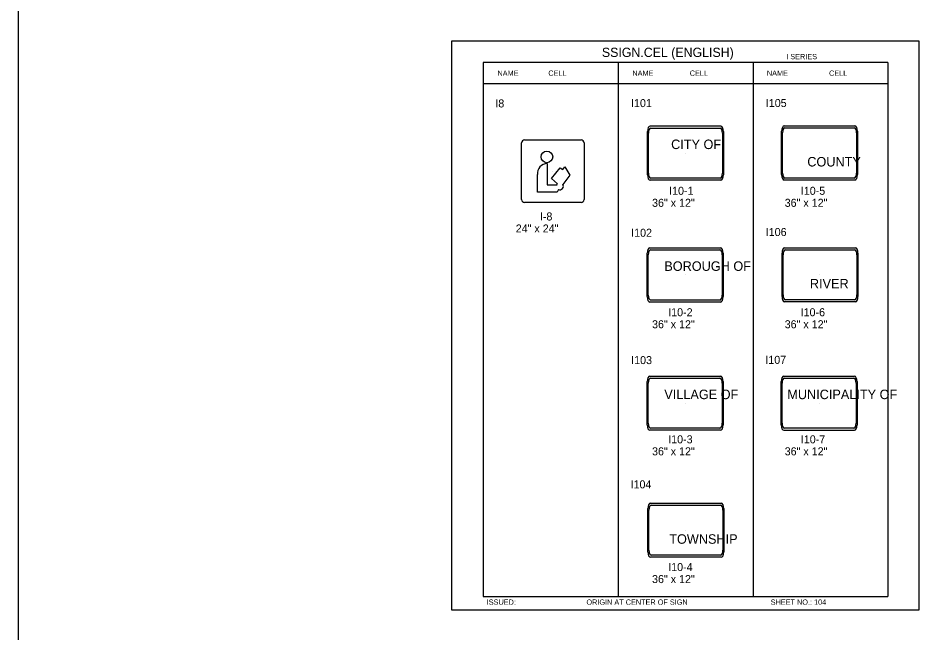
# Model space of a CAD drawing. Extents: x -5299 to 22597, y -19549 to -1808.
# Drawn here: x 13684 to 15035, y -4579 to -3658 of the extents above; entities that cross this region are included whole.
import ezdxf

# ---------------------------------------------------------------- set-up
doc = ezdxf.new("R2010")
doc.units = 0
for name, color, linetype in [('Level 1', 7, 'Continuous'), ('Level 2', 7, 'Continuous'), ('Level 3', 7, 'Continuous'), ('Level 61', 7, 'Continuous')]:
    doc.layers.add(name, color=color, linetype=linetype)

msp = doc.modelspace()

# ---------------------------------------------------------------- linework, layer by layer
at = {"layer": 'Level 1'}
for p, q in [((14988.9, -3724.4), (14381.9, -3724.4)), ((14381.9, -3724.4), (14381.9, -4524.4)), ((14584.3, -3724.4), (14584.3, -4524.4)), ((14786.6, -3724.4), (14786.6, -4524.4)), ((14988.9, -3724.4), (14988.9, -4524.4)), ((14988.9, -3756), (14381.9, -3756)), ((14632.2, -3819.4), (14738.4, -3819.4)), ((14633.3, -3822.5), (14737.3, -3822.5)), ((14833.3, -3819.1), (14939.5, -3819.1)), ((14834.4, -3822.1), (14938.4, -3822.1)), ((14628.4, -3892.6), (14628.4, -3827.6)), ((14629.8, -3890.2), (14629.8, -3830)), ((14740.8, -3830), (14740.8, -3890.2)), ((14742.2, -3827.6), (14742.2, -3892.6)), ((14829.5, -3892.3), (14829.5, -3827.3)), ((14830.9, -3889.9), (14830.9, -3829.7)), ((14941.9, -3829.7), (14941.9, -3889.9)), ((14943.3, -3827.3), (14943.3, -3892.3)), ((14439.6, -3929.6), (14439.6, -3844.7)), ((14444.1, -3840.2), (14528.9, -3840.2)), ((14533.5, -3844.7), (14533.5, -3929.6)), ((14685.3, -3860.1), (14685.3, -3860.1)), ((14886.4, -3859.8), (14886.4, -3859.8)), ((14477.8, -3875.5), (14477.8, -3907.7)), ((14484.6, -3898.2), (14497.5, -3882.2)), ((14486.5, -3887.2), (14486.5, -3887.2)), ((14497.5, -3882.2), (14501.2, -3884.7)), ((14501.2, -3884.7), (14504.6, -3880.6)), ((14504.6, -3880.6), (14512.1, -3893.3)), ((14463.4, -3918.8), (14463.4, -3892.1)), ((14493.4, -3905.9), (14484.6, -3898.2)), ((14512.1, -3893.3), (14501.5, -3907)), ((14738.4, -3900.7), (14632.2, -3900.7)), ((14737.3, -3897.7), (14633.3, -3897.7)), ((14939.5, -3900.4), (14833.3, -3900.4)), ((14938.4, -3897.4), (14834.4, -3897.4)), ((14477.8, -3907.7), (14492.7, -3907.7)), ((14494.9, -3914.5), (14493, -3918.8)), ((14493, -3918.8), (14463.4, -3918.8)), ((14528.9, -3934.1), (14444.1, -3934.1)), ((14628, -4075.1), (14628, -4010)), ((14631.8, -4001.9), (14738, -4001.9)), ((14633, -4004.9), (14736.9, -4004.9)), ((14741.8, -4010), (14741.8, -4075.1)), ((14830.1, -4074.9), (14830.1, -4009.9)), ((14831.6, -4072.5), (14831.6, -4012.3)), ((14833.9, -4001.8), (14940.1, -4001.8)), ((14835.1, -4004.8), (14939, -4004.8)), ((14942.5, -4012.3), (14942.5, -4072.5)), ((14943.9, -4009.9), (14943.9, -4074.9)), ((14629.4, -4072.7), (14629.4, -4012.4)), ((14740.4, -4012.4), (14740.4, -4072.7)), ((14684.9, -4042.5), (14684.9, -4042.5)), ((14887, -4042.4), (14887, -4042.4)), ((14738, -4083.2), (14631.8, -4083.2)), ((14736.9, -4080.2), (14633, -4080.2)), ((14940.1, -4083.1), (14833.9, -4083.1)), ((14939, -4080.1), (14835.1, -4080.1)), ((14631.8, -4194.1), (14738, -4194.1)), ((14633, -4197.1), (14736.9, -4197.1)), ((14832.6, -4194.2), (14938.8, -4194.2)), ((14833.7, -4197.2), (14937.7, -4197.2)), ((14628, -4267.3), (14628, -4202.3)), ((14629.4, -4264.9), (14629.4, -4204.7)), ((14740.4, -4204.7), (14740.4, -4264.9)), ((14741.8, -4202.3), (14741.8, -4267.3)), ((14828.8, -4267.3), (14828.8, -4202.3)), ((14830.2, -4264.9), (14830.2, -4204.7)), ((14941.2, -4204.7), (14941.2, -4264.9)), ((14942.6, -4202.3), (14942.6, -4267.3)), ((14684.9, -4234.8), (14684.9, -4234.8)), ((14885.7, -4234.8), (14885.7, -4234.8)), ((14738, -4275.4), (14631.8, -4275.4)), ((14736.9, -4272.4), (14633, -4272.4)), ((14938.8, -4275.5), (14832.6, -4275.5)), ((14937.7, -4272.4), (14833.7, -4272.4)), ((14632.8, -4384.5), (14739, -4384.5)), ((14634, -4387.5), (14737.9, -4387.5)), ((14629, -4457.6), (14629, -4392.6)), ((14630.5, -4455.2), (14630.5, -4395)), ((14741.4, -4395), (14741.4, -4455.2)), ((14742.8, -4392.6), (14742.8, -4457.6)), ((14685.9, -4425.1), (14685.9, -4425.1)), ((14739, -4465.7), (14632.8, -4465.7)), ((14737.9, -4462.7), (14634, -4462.7)), ((14381.9, -4524.4), (14988.9, -4524.4))]:
    msp.add_line(p, q, dxfattribs=at)
msp.add_circle((14477.5, -3865.7), 8.72, dxfattribs=at)
for centre, radius, start, end in [((14444.1, -3844.7), 4.51, 90, 180), ((14528.9, -3844.7), 4.51, 0, 90), ((14478.9, -3890.9), 15.5, 94.1472, 184.1475), ((14493.4, -3906.9), 1.02, 89.9903, 228.6944), ((14496.9, -3909.7), 5.37, 247.0554, 31.0335), ((14444.1, -3929.6), 4.51, 180, 270), ((14528.9, -3929.6), 4.51, 270, 0)]:
    msp.add_arc(centre, radius, start, end, dxfattribs=at)
for centre, major_axis, start_param, end_param in [((14632.2, -3827.6), (0, -8.13), 3.141593, 4.712389), ((14633.3, -3830), (0, -7.52), 3.141593, 4.712389), ((14737.3, -3830), (0, 7.52), 4.712389, 6.283185), ((14738.4, -3827.6), (0, 8.13), 4.712389, 6.283185), ((14833.3, -3827.3), (0, -8.13), 3.141593, 4.712389), ((14834.4, -3829.7), (0, -7.52), 3.141593, 4.712389), ((14938.4, -3829.7), (0, 7.52), 4.712389, 6.283185), ((14939.5, -3827.3), (0, 8.13), 4.712389, 6.283185), ((14633.3, -3890.2), (0, -7.52), 4.712389, 6.283185), ((14737.3, -3890.2), (0, 7.52), 3.141593, 4.712389), ((14834.4, -3889.9), (0, -7.52), 4.712389, 6.283185), ((14938.4, -3889.9), (0, 7.52), 3.141593, 4.712389), ((14632.2, -3892.6), (0, -8.13), 4.712389, 6.283185), ((14738.4, -3892.6), (0, 8.13), 3.141593, 4.712389), ((14833.3, -3892.3), (0, -8.13), 4.712389, 6.283185), ((14939.5, -3892.3), (0, 8.13), 3.141593, 4.712389), ((14631.8, -4010), (0, -8.13), 3.141593, 4.712389), ((14633, -4012.4), (0, -7.52), 3.141593, 4.712389), ((14736.9, -4012.4), (0, 7.52), 4.712389, 6.283185), ((14738, -4010), (0, 8.13), 4.712389, 6.283185), ((14833.9, -4009.9), (0, -8.13), 3.141593, 4.712389), ((14835.1, -4012.3), (0, -7.52), 3.141593, 4.712389), ((14939, -4012.3), (0, 7.52), 4.712389, 6.283185), ((14940.1, -4009.9), (0, 8.13), 4.712389, 6.283185), ((14631.8, -4075.1), (0, -8.13), 4.712389, 6.283185), ((14633, -4072.7), (0, -7.52), 4.712389, 6.283185), ((14736.9, -4072.7), (0, 7.52), 3.141593, 4.712389), ((14738, -4075.1), (0, 8.13), 3.141593, 4.712389), ((14833.9, -4074.9), (0, -8.13), 4.712389, 6.283185), ((14835.1, -4072.5), (0, -7.52), 4.712389, 6.283185), ((14939, -4072.5), (0, 7.52), 3.141593, 4.712389), ((14940.1, -4074.9), (0, 8.13), 3.141593, 4.712389), ((14631.8, -4202.3), (0, -8.13), 3.141593, 4.712389), ((14633, -4204.7), (0, -7.52), 3.141593, 4.712389), ((14736.9, -4204.7), (0, 7.52), 4.712389, 6.283185), ((14738, -4202.3), (0, 8.13), 4.712389, 6.283185), ((14832.6, -4202.3), (0, -8.13), 3.141593, 4.712389), ((14833.7, -4204.7), (0, -7.52), 3.141593, 4.712389), ((14937.7, -4204.7), (0, 7.52), 4.712389, 6.283185), ((14938.8, -4202.3), (0, 8.13), 4.712389, 6.283185), ((14631.8, -4267.3), (0, -8.13), 4.712389, 6.283185), ((14633, -4264.9), (0, -7.52), 4.712389, 6.283185), ((14736.9, -4264.9), (0, 7.52), 3.141593, 4.712389), ((14738, -4267.3), (0, 8.13), 3.141593, 4.712389), ((14832.6, -4267.3), (0, -8.13), 4.712389, 6.283185), ((14833.7, -4264.9), (0, -7.52), 4.712389, 6.283185), ((14937.7, -4264.9), (0, 7.52), 3.141593, 4.712389), ((14938.8, -4267.3), (0, 8.13), 3.141593, 4.712389), ((14632.8, -4392.6), (0, -8.13), 3.141593, 4.712389), ((14634, -4395), (0, -7.52), 3.141593, 4.712389), ((14737.9, -4395), (0, 7.52), 4.712389, 6.283185), ((14739, -4392.6), (0, 8.13), 4.712389, 6.283185), ((14632.8, -4457.6), (0, -8.13), 4.712389, 6.283185), ((14634, -4455.2), (0, -7.52), 4.712389, 6.283185), ((14737.9, -4455.2), (0, 7.52), 3.141593, 4.712389), ((14739, -4457.6), (0, 8.13), 3.141593, 4.712389)]:
    msp.add_ellipse(centre, major_axis=major_axis, ratio=0.4667, start_param=start_param, end_param=end_param, dxfattribs=at)
at = {"layer": 'Level 3'}
msp.add_line((13684.5, -1877.7), (13684.5, -9425.7), dxfattribs=at)
at = {"layer": 'Level 61'}
msp.add_lwpolyline([(14334.4, -4544.5), (15035.5, -4544.5), (15035.5, -3692.2), (14334.4, -3692.2)], close=True, dxfattribs=at)

# ---------------------------------------------------------------- texts
at = {"layer": 'Level 1'}
for s, height, p in [('CITY OF', 14.22, (14663.8, -3854)), ('COUNTY', 14.22, (14868, -3880.1)), ('BOROUGH OF', 14.22, (14653.6, -4036.5)), ('RIVER', 14.22, (14871.9, -4062.8)), ('VILLAGE OF', 14.22, (14653.6, -4228.7)), ('MUNICIPALITY OF', 14.223, (14838, -4228.7)), ('TOWNSHIP', 14.22, (14661, -4445.4))]:
    msp.add_text(s, height=height, dxfattribs=at).set_placement(p)
at = {"layer": 'Level 2'}
for s, p in [('I8', (14400.2, -3791.6)), ('I101', (14603.7, -3791.1)), ('I105', (14805.8, -3791)), ('I102', (14603.9, -3985.4)), ('I106', (14805.7, -3984.3)), ('I103', (14603.9, -4176.2)), ('I107', (14805.1, -4175.8)), ('I104', (14603, -4362.4))]:
    msp.add_text(s, height=12, dxfattribs=at).set_placement(p)
at = {"layer": 'Level 3'}
for s, height, p in [('SSIGN.CEL (ENGLISH)', 13.857, (14560, -3716)), ('I SERIES', 7.92, (14836.4, -3719.4)), ('NAME', 7.92, (14403.4, -3744.2)), ('CELL', 7.92, (14479.7, -3744.2)), ('NAME', 7.92, (14605.7, -3744.2)), ('CELL', 7.92, (14691.7, -3744.2)), ('NAME', 7.92, (14807.4, -3744.2)), ('CELL', 7.92, (14900.6, -3744.2)), ('I10-1', 12, (14660.8, -3922.5)), ('I10-5', 12, (14858.3, -3922.5)), ('36" x 12"', 12, (14635.2, -3940.5)), ('36" x 12"', 12, (14834.1, -3940.5)), ('I-8', 12, (14467, -3961)), ('24" x 24"', 12, (14430.8, -3979)), ('I10-2', 12, (14659.4, -4104.5)), ('I10-6', 12, (14858, -4104.5)), ('36" x 12"', 12, (14635.2, -4122.5)), ('36" x 12"', 12, (14834.1, -4122.5)), ('I10-3', 12, (14659.4, -4294.9)), ('I10-7', 12, (14858.3, -4294.9)), ('36" x 12"', 12, (14635.2, -4312.9)), ('36" x 12"', 12, (14834.1, -4312.9)), ('I10-4', 12, (14659.4, -4486.3)), ('36" x 12"', 12, (14635.2, -4504.3)), ('ISSUED:', 7.92, (14387.3, -4536.8)), ('ORIGIN AT CENTER OF SIGN', 7.918, (14536.8, -4536.8)), ('SHEET NO.: 104', 7.918, (14813.1, -4536.8))]:
    msp.add_text(s, height=height, dxfattribs=at).set_placement(p)

doc.saveas('drawing.dxf')
